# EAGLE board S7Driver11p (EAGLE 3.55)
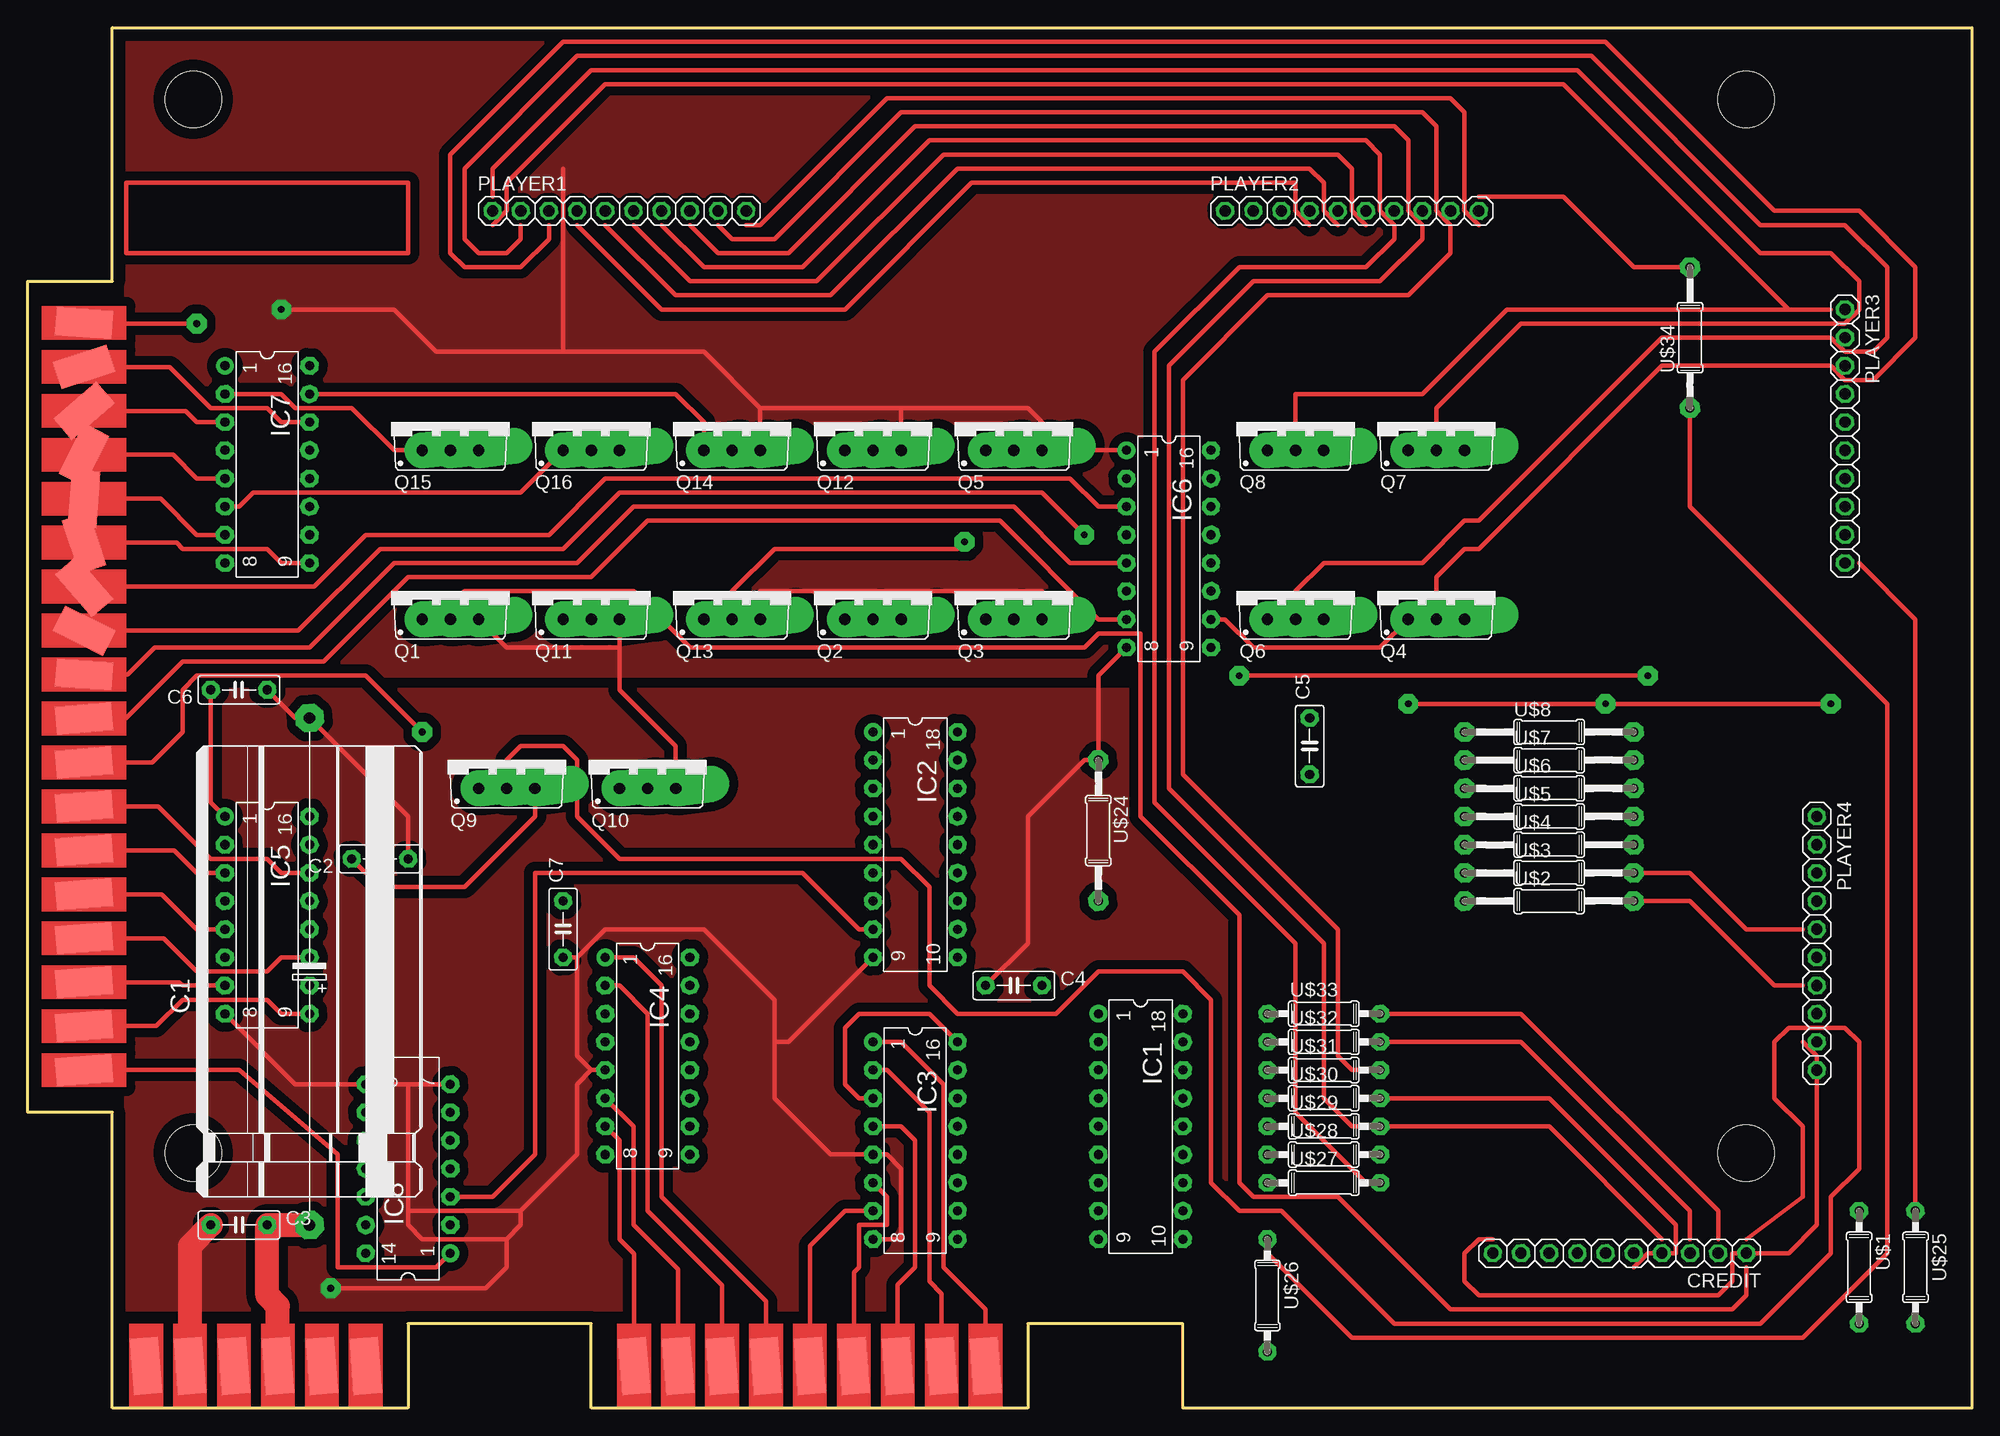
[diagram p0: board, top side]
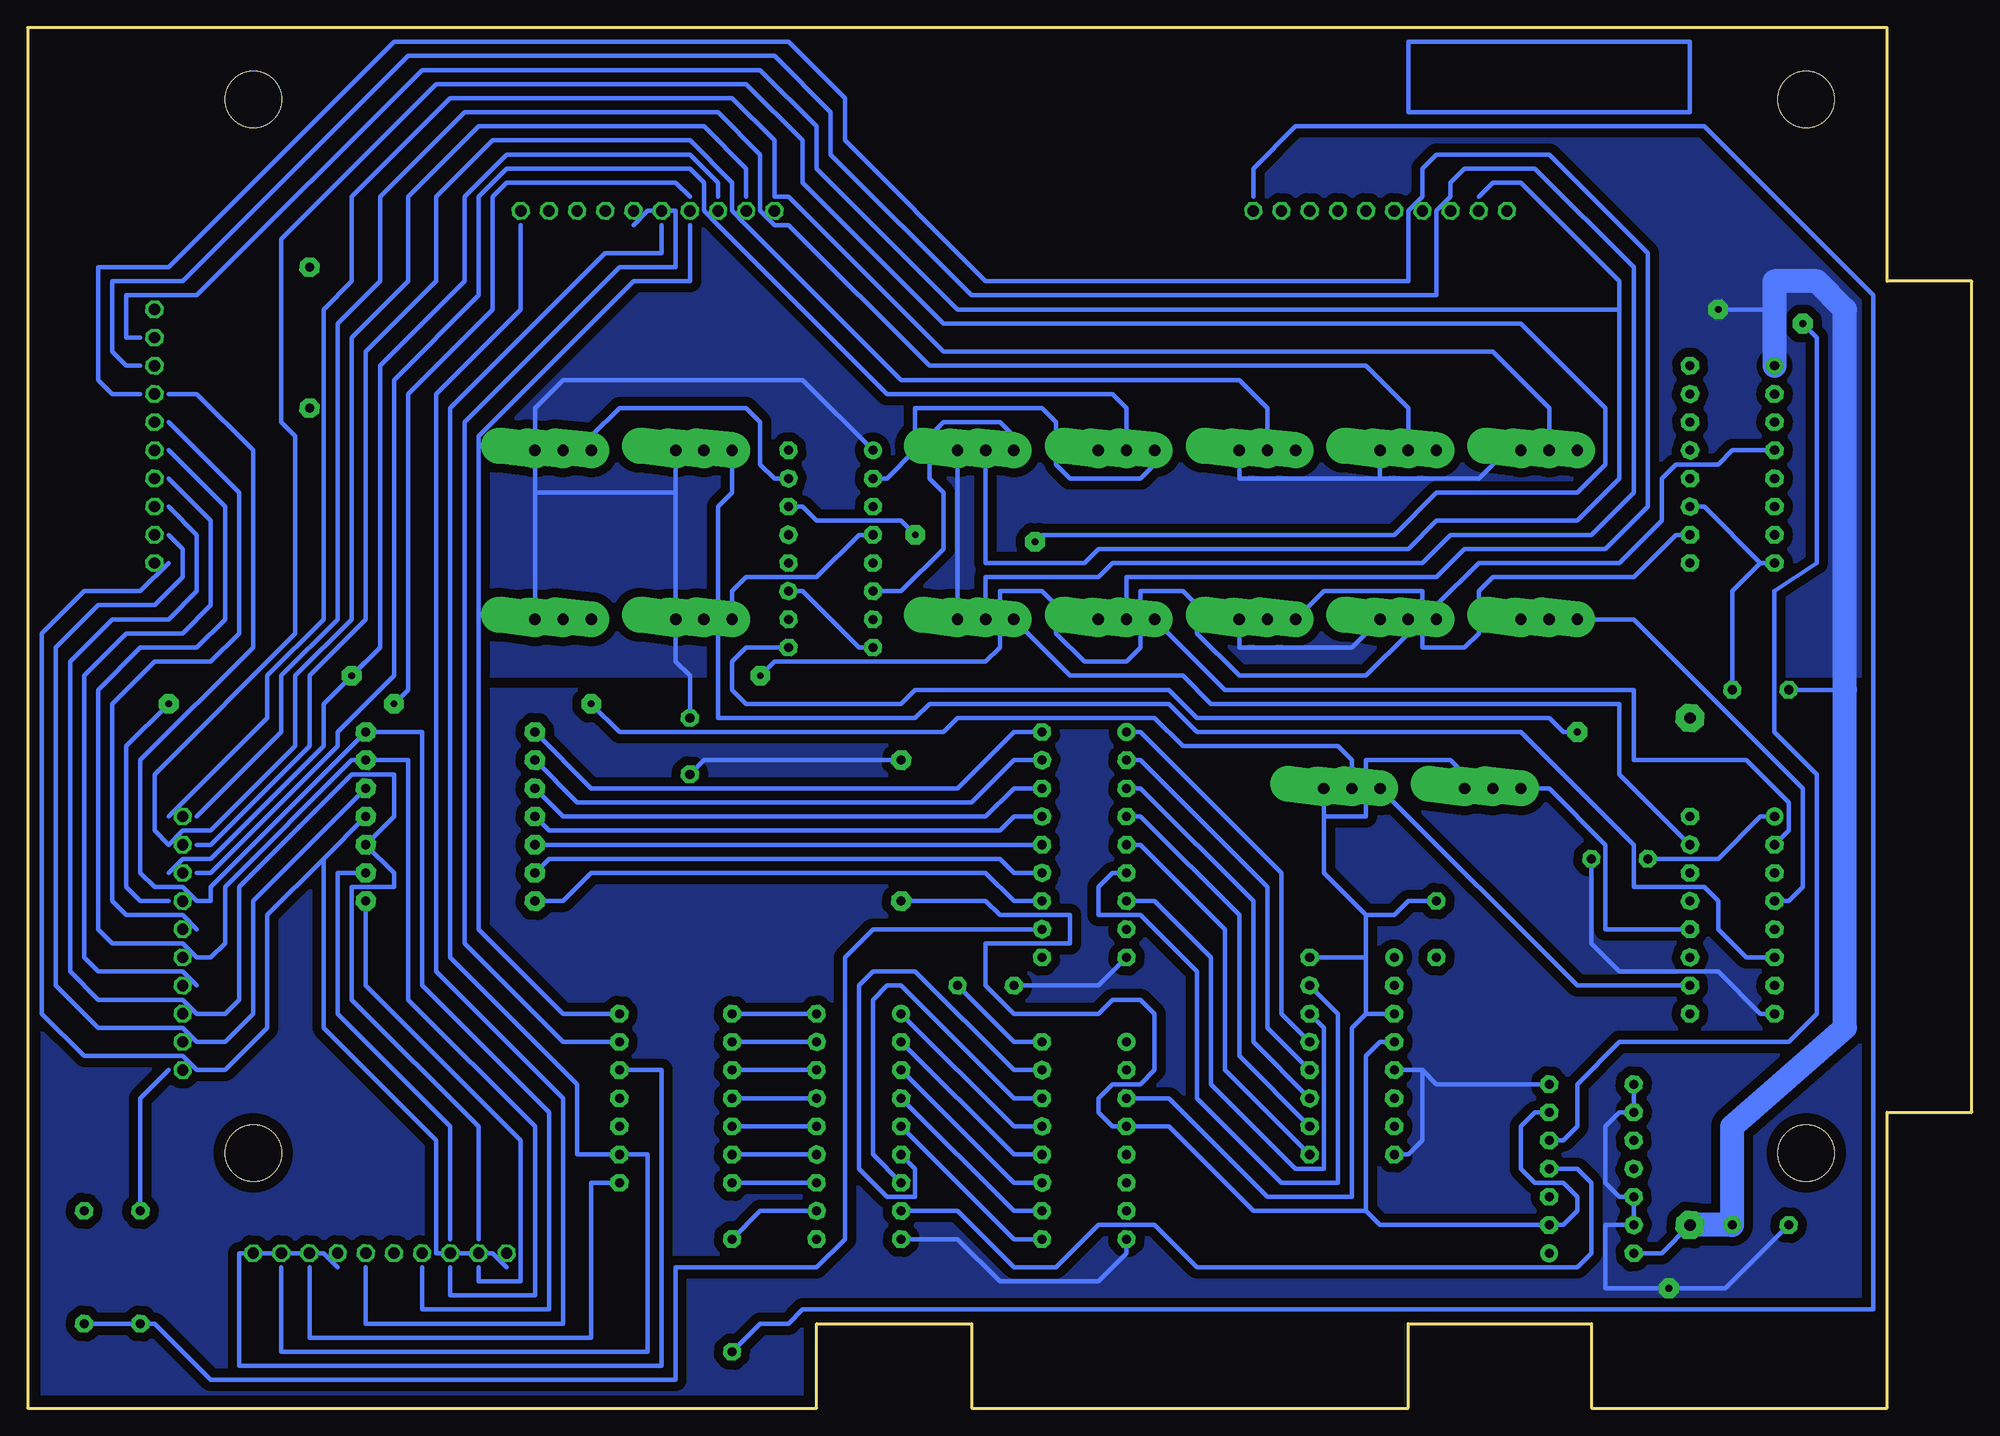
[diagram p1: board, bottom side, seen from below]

Size 175.26 x 124.46 mm. Coordinates in mm from the lower left corner, seen from the top.
Outline: 7.62,0 7.62,26.67 0,26.67 0,101.6 7.62,101.6 7.62,124.46 175.26,124.46 175.26,0 104.14,0 104.14,7.62 90.17,7.62 90.17,0 50.8,0 50.8,7.62 34.29,7.62 34.29,0 7.62,0
Copper layers used: Top, Bottom
Holes 5.08 mm at 14.92,23 154.92,23 154.92,118 14.92,118

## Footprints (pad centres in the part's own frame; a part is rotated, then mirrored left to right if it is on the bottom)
ATINE9 = smd 2.54 x 5.08 rotated 4.3:  0,0 | smd 2.54 x 5.08 rotated 4.4:  3.962,0 | smd 2.54 x 5.08 rotated 4.5:  7.925,0 | smd 2.54 x 5.08 rotated 4.6:  11.887,0 | smd 2.54 x 5.08 rotated 4.7:  15.85,0;  19.812,0 | smd 2.54 x 5.08 rotated 4.8:  23.774,0 | smd 2.54 x 5.08 rotated 4.9:  27.737,0 | smd 2.54 x 5.08 rotated 5:  31.699,0
45 = drill 1.016 pad 2.54 octagon:  0,0;  45.72,0
B2,5 = drill 0.813 pad 1.6 octagon:  -2.54,0;  2.54,0
10 = drill 1.016 pad 1.6 octagon:  -11.43,0;  -8.89,0;  -6.35,0;  -3.81,0;  -1.27,0;  1.27,0;  3.81,0;  6.35,0;  8.89,0;  11.43,0
L18 = drill 0.813 pad 1.6 round:  -10.16,-3.81 | drill 0.813 pad 1.6 octagon:  -7.62,-3.81;  -5.08,-3.81;  -2.54,-3.81;  0,-3.81;  2.54,-3.81;  5.08,-3.81;  7.62,-3.81;  10.16,-3.81;  10.16,3.81;  7.62,3.81;  5.08,3.81;  2.54,3.81;  0,3.81;  -2.54,3.81;  -5.08,3.81;  -7.62,3.81;  -10.16,3.81
L16 = drill 0.813 pad 1.6 round:  -8.89,-3.81 | drill 0.813 pad 1.6 octagon:  -6.35,-3.81;  -3.81,-3.81;  -1.27,-3.81;  1.27,-3.81;  3.81,-3.81;  6.35,-3.81;  8.89,-3.81;  8.89,3.81;  6.35,3.81;  3.81,3.81;  1.27,3.81;  -1.27,3.81;  -3.81,3.81;  -6.35,3.81;  -8.89,3.81
L16' = drill 0.813 pad 1.6 round:  -8.89,-3.81 | drill 0.813 pad 1.6 octagon:  -6.35,-3.81;  6.35,-3.81;  8.89,-3.81;  -3.81,-3.81;  -1.27,-3.81;  3.81,-3.81;  1.27,-3.81;  8.89,3.81;  6.35,3.81;  3.81,3.81;  1.27,3.81;  -1.27,3.81;  -3.81,3.81;  -6.35,3.81;  -8.89,3.81
L14 = drill 0.813 pad 1.6 round:  -7.62,-3.81 | drill 0.813 pad 1.6 octagon:  -5.08,-3.81;  7.62,-3.81;  7.62,3.81;  -2.54,-3.81;  0,-3.81;  5.08,-3.81;  2.54,-3.81;  5.08,3.81;  2.54,3.81;  0,3.81;  -2.54,3.81;  -5.08,3.81;  -7.62,3.81
ATINE6 = smd 2.54 x 5.08 rotated 4.3:  0,0 | smd 2.54 x 5.08 rotated 4.4:  3.962,0 | smd 2.54 x 5.08 rotated 4.5:  7.925,0 | smd 2.54 x 5.08 rotated 4.6:  11.887,0 | smd 2.54 x 5.08 rotated 4.7:  15.85,0;  19.812,0
220BS = drill 1.016 pad 3.251 offset:  -2.54,-2.54;  0,-2.54;  2.54,-2.54
TINE18 = smd 2.54 x 5.08 rotated 4.3:  0,0;  35.662,0 | smd 2.54 x 5.08 rotated 4.4:  3.962,0 | smd 2.54 x 5.08 rotated 4.5:  7.925,0 | smd 2.54 x 5.08 rotated 4.6:  11.887,0 | smd 2.54 x 5.08 rotated 4.7:  15.85,0;  19.812,0 | smd 2.54 x 5.08 rotated 4.8:  23.774,0 | smd 2.54 x 5.08 rotated 4.9:  27.737,0 | smd 2.54 x 5.08 rotated 5:  31.699,0 | smd 2.54 x 5.08 rotated 26.8:  39.624,0 | smd 2.54 x 5.08 rotated 49.3:  43.586,0 | smd 2.54 x 5.08 rotated 71.8:  47.549,0 | smd 2.54 x 5.08 rotated 94.3:  51.511,0 | smd 2.54 x 5.08 rotated 116.8:  55.474,0 | smd 2.54 x 5.08 rotated 139.3:  59.436,0 | smd 2.54 x 5.08 rotated 161.8:  63.398,0 | smd 2.54 x 5.08 rotated 184.3:  67.361,0
07/10 = drill 0.813 pad 1.6 octagon:  -5.08,0;  5.08,0
07/15A = drill 0.813 pad 1.778 octagon:  -7.62,0;  7.62,0
07/12A = drill 0.813 pad 1.778 octagon:  -6.35,0;  6.35,0

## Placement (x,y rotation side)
BCD-IN  PADROW9  [ATINE9]  86.36,3.81 180 top
C1  ELC-45  [45]  25.4,16.51 90 top
C2  C2,5  [B2,5]  31.75,49.53 180 top
C3  C2,5  [B2,5]  19.05,16.51 0 top
C4  C2,5  [B2,5]  88.9,38.1 0 top
C5  C2,5  [B2,5]  115.57,59.69 90 top
C6  C2,5  [B2,5]  19.05,64.77 180 top
C7  C2,5  [B2,5]  48.26,43.18 90 top
CREDIT  PINHD-2X10  [10]  143.51,13.97 180 top
IC1  ULN2803  [L18]  100.33,25.4 270 top
IC2  ULN2803  [L18]  80.01,50.8 270 top
IC3  4511  [L16]  80.01,24.13 270 top
IC4  4511  [L16]  55.88,31.75 270 top
IC5  4050  [L16']  21.59,44.45 270 top
IC6  4050  [L16']  102.87,77.47 270 top
IC7  4050  [L16']  21.59,85.09 270 top
IC8  4081  [L14]  34.29,21.59 90 top
PLAYER1  PINHD-2X10  [10]  53.34,107.95 0 top
PLAYER2  PINHD-2X10  [10]  119.38,107.95 0 top
PLAYER3  PINHD-2X10  [10]  163.83,87.63 270 top
PLAYER4  PINHD-2X10  [10]  161.29,41.91 270 top
POWER  PADROW6  [ATINE6]  30.48,3.81 180 top
Q1  IRF????  [220BS]  38.1,73.66 0 top
Q2  IRF????  [220BS]  76.2,73.66 0 top
Q3  IRF????  [220BS]  88.9,73.66 0 top
Q4  IRF????  [220BS]  127,73.66 0 top
Q5  IRF????  [220BS]  88.9,88.9 0 top
Q6  IRF????  [220BS]  114.3,73.66 0 top
Q7  IRF????  [220BS]  127,88.9 0 top
Q8  IRF????  [220BS]  114.3,88.9 0 top
Q9  IRF????  [220BS]  43.18,58.42 0 top
Q10  IRF????  [220BS]  55.88,58.42 0 top
Q11  IRF????  [220BS]  50.8,73.66 0 top
Q12  IRF????  [220BS]  76.2,88.9 0 top
Q13  IRF????  [220BS]  63.5,73.66 0 top
Q14  IRF????  [220BS]  63.5,88.9 0 top
Q15  IRF????  [220BS]  38.1,88.9 0 top
Q16  IRF????  [220BS]  50.8,88.9 0 top
STROBE  PADROW18  [TINE18]  5.08,30.48 90 top
U$1  R1206  [07/10]  165.1,12.7 270 top
U$2  R1206  [07/15A]  137.16,45.72 0 top
U$3  R1206  [07/15A]  137.16,48.26 0 top
U$4  R1206  [07/15A]  137.16,50.8 0 top
U$5  R1206  [07/15A]  137.16,53.34 0 top
U$6  R1206  [07/15A]  137.16,55.88 0 top
U$7  R1206  [07/15A]  137.16,58.42 0 top
U$8  R1206  [07/15A]  137.16,60.96 0 top
U$24  6.8K  [07/12A]  96.52,52.07 270 top
U$25  R1206  [07/10]  170.18,12.7 270 top
U$26  R1206  [07/10]  111.76,10.16 270 top
U$27  R1206  [07/10]  116.84,20.32 0 top
U$28  R1206  [07/10]  116.84,22.86 0 top
U$29  R1206  [07/10]  116.84,25.4 0 top
U$30  R1206  [07/10]  116.84,27.94 0 top
U$31  R1206  [07/10]  116.84,30.48 0 top
U$32  R1206  [07/10]  116.84,33.02 0 top
U$33  R1206  [07/10]  116.84,35.56 0 top
U$34  R1206  [07/12A]  149.86,96.52 90 top

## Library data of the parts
BCD-IN POWER STROBE = SPECIAL
C1 = DISCRETE
C2-C7 = CAP
CREDIT PLAYER1-PLAYER4 = PINHEAD
IC1-IC4 = ULN
IC5-IC8 = 40XX
Q1-Q16 = TRANS-PW
U$1-U$8 U$24-U$34 = R

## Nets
BLANKING: BCD-IN. IC3. IC4. IC8. U$24.
GND: C1. C2. C3. C4. C5. C6. C7. IC1. IC2. IC3. IC4. IC5. IC6. IC7. IC8. POWER. U$24.
KOMMA1: PLAYER1. U$26.
KOMMA2: PLAYER2. U$34.
KOMMA3: PLAYER3. U$25.
KOMMA4: PLAYER4. U$1.
KOMMA12: IC8. STROBE.
KOMMA34: IC8. STROBE.
N$1: IC1. U$26. U$34.
N$2: IC1. U$27.
N$3: IC1. U$28.
N$4: IC1. U$29.
N$5: IC1. U$30.
N$6: IC1. U$31.
N$7: IC1. U$32.
N$8: IC1. U$33.
N$9: IC2. U$1. U$25.
N$10: IC2. U$4.
N$11: IC2. U$5.
N$12: IC2. U$6.
N$13: IC2. U$7.
N$14: IC2. U$8.
N$15: IC2. U$2.
N$16: IC2. U$3.
N$17: BCD-IN. IC3.
N$18: BCD-IN. IC3.
N$19: BCD-IN. IC3.
N$20: BCD-IN. IC4.
N$21: BCD-IN. IC4.
N$22: BCD-IN. IC4.
N$23: BCD-IN. IC4.
N$24: IC1. IC8.
N$25: BCD-IN. IC3.
N$26: IC5. Q9.
N$27: IC5. Q10.
N$28: IC7. Q11.
N$29: IC6. Q12.
N$30: IC7. Q13.
N$31: IC7. Q14.
N$32: IC7. Q15.
N$33: IC7. Q16.
N$34: IC5. Q1.
N$35: IC5. Q2.
N$36: IC5. Q3.
N$37: IC6. Q4.
N$38: IC6. Q5.
N$39: IC6. Q6.
N$40: IC6. Q7.
N$41: IC5. Q8.
N$48: IC2. IC8.
P1A: CREDIT. PLAYER1. PLAYER2. U$33.
P1B: CREDIT. PLAYER1. PLAYER2. U$32.
P1C: CREDIT. PLAYER1. PLAYER2. U$31.
P1D: CREDIT. PLAYER1. PLAYER2. U$30.
P1E: CREDIT. PLAYER1. PLAYER2. U$29.
P1F: CREDIT. PLAYER1. PLAYER2. U$28.
P1G: CREDIT. PLAYER1. PLAYER2. U$27.
P2A: CREDIT. PLAYER3. PLAYER4. U$8.
P2B: CREDIT. PLAYER3. PLAYER4. U$7.
P2C: CREDIT. PLAYER3. PLAYER4. U$6.
P2D: CREDIT. PLAYER3. PLAYER4. U$5.
P2E: CREDIT. PLAYER3. PLAYER4. U$4.
P2F: CREDIT. PLAYER3. PLAYER4. U$3.
P2G: CREDIT. PLAYER3. PLAYER4. U$2.
STR1: CREDIT. Q1.
STR2: PLAYER1. PLAYER3. Q2.
STR3: PLAYER1. PLAYER3. Q3.
STR4: PLAYER1. PLAYER3. Q4.
STR5: PLAYER1. PLAYER3. Q5.
STR6: PLAYER1. PLAYER3. Q6.
STR7: PLAYER1. PLAYER3. Q7.
STR8: PLAYER1. PLAYER3. Q8.
STR9: CREDIT. Q9.
STR10: PLAYER2. PLAYER4. Q10.
STR11: PLAYER2. PLAYER4. Q11.
STR12: PLAYER2. PLAYER4. Q12.
STR13: PLAYER2. PLAYER4. Q13.
STR14: PLAYER2. PLAYER4. Q14.
STR15: PLAYER2. PLAYER4. Q15.
STR16: PLAYER2. PLAYER4. Q16.
VCC: C1. C2. C3. C4. C5. C6. C7. IC3. IC4. IC5. IC6. IC7. IC8. POWER. Q1. Q2. Q3. Q4. Q5. Q6. Q7. Q8. Q9. Q10. Q11. Q12. Q13. Q14. Q15. Q16.
W1A: IC1. IC3.
W1B: IC1. IC3.
W1C: IC1. IC3.
W1D: IC1. IC3.
W1E: IC1. IC3.
W1F: IC1. IC3.
W1G: IC1. IC3.
W2A: IC2. IC4.
W2B: IC2. IC4.
W2C: IC2. IC4.
W2D: IC2. IC4.
W2E: IC2. IC4.
W2F: IC2. IC4.
W2G: IC2. IC4.
WSTR1: IC5. STROBE.
WSTR2: IC5. STROBE.
WSTR3: IC5. STROBE.
WSTR4: IC6. STROBE.
WSTR5: IC6. STROBE.
WSTR6: IC6. STROBE.
WSTR7: IC6. STROBE.
WSTR8: IC5. STROBE.
WSTR9: IC5. STROBE.
WSTR10: IC5. STROBE.
WSTR11: IC7. STROBE.
WSTR12: IC6. STROBE.
WSTR13: IC7. STROBE.
WSTR14: IC7. STROBE.
WSTR15: IC7. STROBE.
WSTR16: IC7. STROBE.

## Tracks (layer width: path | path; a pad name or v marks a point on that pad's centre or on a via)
BLANKING
  Top 0.406: 76.2,25.4 78.74,25.4 80.01,24.13 80.01,12.7 78.44,11.12 78.44,3.81
  Bottom 0.406: 52.07,33.02 53.34,33.02 54.61,31.75 54.61,17.78 | 54.61,17.78 64.77,17.78 72.39,25.4 76.2,25.4 77.47,25.4 78.74,26.67 78.74,27.94 77.47,29.21 74.93,29.21 73.66,30.48 73.66,35.56 74.93,36.83 77.47,36.83 78.74,35.56 86.36,35.56 88.9,38.1 88.9,41.91 81.28,41.91 81.28,44.45 87.63,44.45 88.9,45.72 U$24. | 54.61,17.78 53.34,16.51 38.1,16.51 36.83,16.51 35.56,17.78 35.56,19.05 36.83,20.32 39.37,20.32 40.64,21.59 40.64,25.4 39.37,26.67 38.1,26.67
GND  (via drill 0.61 pad 1.78)
  Top 0.406: 67.31,33.02 67.31,27.94 72.39,22.86 76.2,22.86 77.47,22.86 78.74,21.59 78.74,15.24 76.2,15.24 | 67.31,33.02 67.31,36.83 60.96,43.18 52.07,43.18 49.53,40.64 | 49.53,40.64 49.53,31.75 50.8,30.48 | 50.8,30.48 52.07,30.48 | 17.78,35.56 24.13,29.21 30.48,29.21 34.29,29.21 | 34.29,29.21 38.1,29.21 | 67.31,33.02 68.58,33.02 76.2,40.64 | 99.06,68.58 96.52,66.04 96.52,58.42 95.25,58.42 90.17,53.34 90.17,41.91 86.36,38.1 | 49.53,40.64 48.26,40.64 | 50.8,30.48 49.53,29.21 49.53,22.86 44.45,17.78 | 44.45,17.78 44.45,16.51 43.18,15.24 | 43.18,15.24 35.56,15.24 34.29,16.51 34.29,17.78 | 34.29,17.78 34.29,29.21 | 44.45,17.78 34.29,17.78 | 21.59,64.77 24.13,62.23 C1. 34.29,53.34 34.29,49.53 | v27.3,10.79 41.27,10.79 43.18,12.7 43.18,15.24
  Top 2.184: 14.63,3.81 14.63,14.63 16.51,16.51
  Bottom 0.406: 25.4,81.28 24.13,81.28 19.05,76.2 | 19.05,76.2 17.78,76.2 | 30.48,29.21 30.48,26.67 31.75,26.67 33.02,25.4 33.02,20.32 31.75,19.05 30.48,19.05 30.48,16.51 33.02,16.51 33.02,10.79 v27.3,10.79 22.23,10.79 16.51,16.51 | 38.1,29.21 48.26,29.21 49.53,30.48 | 52.07,30.48 49.53,30.48 | 52.07,22.86 50.8,22.86 49.53,24.13 49.53,30.48 | 106.68,73.66 105.41,73.66 100.33,68.58 99.06,68.58 | 76.2,15.24 76.2,13.97 78.74,11.43 87.63,11.43 91.44,15.24 96.52,15.24 | 19.05,76.2 21.59,73.66 21.59,64.77 | 17.78,35.56 19.05,35.56 22.86,39.37 31.75,39.37 34.29,41.91 34.29,49.53 | 96.52,58.42 114.3,58.42 115.57,57.15 | 76.2,40.64 78.74,38.1 86.36,38.1
  pour Bottom (isolate 0.8): 8.89,8.89 8.89,64.77 137.16,64.77 137.16,91.44 50.8,91.44 50.8,124.46 175.26,124.46 175.26,0 104.14,0 104.14,8.89
  pour Top (isolate 0.8): 8.89,8.89 8.89,64.77 140.97,64.77 140.97,124.46 175.26,124.46 175.26,0 104.14,0 104.14,8.89
KOMMA1
  Bottom 0.406: U$26. 109.22,7.62 106.68,7.62 105.41,8.89 8.89,8.89 8.89,100.33 24.13,115.57 60.96,115.57 64.77,111.76 64.77,109.22
KOMMA2
  Top 0.406: 130.81,109.22 138.43,109.22 144.78,102.87 U$34.
KOMMA3
  Top 0.406: 165.1,76.2 170.18,71.12 170.18,17.78
KOMMA4
  Bottom 0.406: 165.1,17.78 165.1,27.94 162.56,30.48
KOMMA12  (via drill 0.61 pad 1.78)
  Top 0.406: STROBE. 5.08,97.79 v15.24,97.79
  Bottom 0.406: 38.1,24.13 36.83,24.13 35.56,25.4 35.56,29.21 31.75,33.02 16.51,33.02 13.97,35.56 13.97,57.15 17.78,60.96 17.78,73.66 13.97,76.2 13.97,96.52 v15.24,97.79
KOMMA34
  Top 0.406: 5.08,30.48 19.05,30.48 27.94,22.86 27.94,12.7 36.83,12.7 38.1,13.97
N$1
  Top 0.406: 111.76,15.24 111.76,13.97 119.38,6.35 160.02,6.35 167.64,13.97 167.64,63.5 149.86,81.28 149.86,90.17
  Bottom 0.406: 104.14,17.78 109.22,17.78 111.76,15.24
N$2
  Bottom 0.406: 104.14,20.32 111.76,20.32
N$3
  Bottom 0.406: 104.14,22.86 111.76,22.86
N$4
  Bottom 0.406: 104.14,25.4 111.76,25.4
N$5
  Bottom 0.406: 104.14,27.94 111.76,27.94
N$6
  Bottom 0.406: 104.14,30.48 111.76,30.48
N$7
  Bottom 0.406: 104.14,33.02 111.76,33.02
N$8
  Bottom 0.406: IC1. 111.76,35.56
N$9
  Bottom 0.406: U$25. U$1. 163.83,7.62 158.75,2.54 116.84,2.54 116.84,12.7 104.14,12.7 101.6,15.24 101.6,40.64 99.06,43.18 83.82,43.18
N$10
  Bottom 0.406: 83.82,50.8 129.54,50.8
N$11
  Bottom 0.406: 83.82,53.34 86.36,53.34 87.63,52.07 128.27,52.07 129.54,53.34
N$12
  Bottom 0.406: 83.82,55.88 86.36,55.88 88.9,53.34 127,53.34 129.54,55.88
N$13
  Bottom 0.406: 83.82,58.42 86.36,58.42 90.17,54.61 125.73,54.61 129.54,58.42
N$14
  Bottom 0.406: IC2. 86.36,60.96 91.44,55.88 124.46,55.88 129.54,60.96
N$15
  Bottom 0.406: 83.82,45.72 86.36,45.72 88.9,48.26 124.46,48.26 127,45.72 129.54,45.72
N$16
  Bottom 0.406: 83.82,48.26 86.36,48.26 87.63,49.53 128.27,49.53 129.54,48.26
N$17
  Top 0.406: 82.4,3.81 82.4,10.31 81.28,11.43 81.28,26.67 77.47,30.48 76.2,30.48
N$18
  Top 0.406: 76.2,20.32 77.47,19.05 77.47,16.51 74.93,16.51 74.93,12.7 74.47,12.24 74.47,3.81
N$19
  Top 0.406: 70.51,3.81 70.51,14.63 73.66,17.78 76.2,17.78
N$20
  Top 0.406: 66.55,3.81 66.55,9.65 57.15,19.05 57.15,38.1 54.61,40.64 52.07,40.64
N$21
  Top 0.406: 62.59,3.81 62.59,11.07 55.88,17.78 55.88,35.56 53.34,38.1 52.07,38.1
N$22
  Top 0.406: 58.62,3.81 58.62,12.5 54.61,16.51 54.61,25.4 52.07,27.94
N$23
  Top 0.406: BCD-IN. 54.66,13.92 53.34,15.24 53.34,24.13 52.07,25.4
N$24
  Bottom 0.406: 38.1,21.59 35.56,21.59 34.29,20.32 34.29,13.97 35.56,12.7 69.85,12.7 73.66,16.51 78.74,16.51 82.55,12.7 86.36,12.7 91.44,17.78 96.52,17.78
N$25
  Top 0.406: 86.36,3.81 86.36,8.89 82.55,12.7 82.55,29.21 78.74,33.02 76.2,33.02
N$26
  Bottom 0.406: 25.4,43.18 33.02,43.18 33.02,50.8 38.1,55.88 40.64,55.88
N$27
  Bottom 0.406: 25.4,38.1 35.56,38.1 53.34,55.88
N$28
  Bottom 0.406: 17.78,86.36 21.59,86.36 22.86,85.09 26.67,85.09 27.94,83.82 27.94,80.01 31.75,76.2 44.45,76.2 48.26,72.39 48.26,71.12
N$29
  Bottom 0.406: 73.66,86.36 73.66,85.09 74.93,83.82 81.28,83.82 82.55,85.09 82.55,88.9 83.82,90.17 95.25,90.17 95.25,86.36 97.79,83.82 99.06,83.82
N$30
  Bottom 0.406: 25.4,78.74 26.67,78.74 30.48,74.93 43.18,74.93 44.45,73.66 44.45,69.85 45.72,68.58 49.53,68.58 49.53,73.66 58.42,73.66 60.96,71.12
N$31
  Top 0.406: 25.4,91.44 58.42,91.44 60.96,88.9 60.96,86.36
N$32
  Top 0.406: 17.78,91.44 22.86,91.44 24.13,90.17 29.21,90.17 33.02,86.36 35.56,86.36
N$33
  Top 0.406: 17.78,81.28 19.05,81.28 20.32,82.55 44.45,82.55 48.26,86.36
N$34
  Bottom 0.406: 17.78,45.72 16.51,45.72 15.24,46.99 15.24,55.88 30.48,71.12 35.56,71.12
N$35
  Bottom 0.406: 17.78,50.8 16.51,52.07 16.51,54.61 20.32,58.42 30.48,58.42 30.48,64.77 67.31,64.77 73.66,71.12
N$36
  Bottom 0.406: 25.4,50.8 31.75,57.15 31.75,63.5 68.58,63.5 71.12,66.04 81.28,66.04 86.36,71.12
N$37
  Top 0.406: 106.68,71.12 107.95,71.12 110.49,68.58 121.92,68.58 124.46,71.12
N$38
  Bottom 0.406: 86.36,86.36 86.36,87.63 87.63,88.9 92.71,88.9 93.98,87.63 93.98,83.82 92.71,82.55 92.71,77.47 96.52,73.66 99.06,73.66
N$39
  Bottom 0.406: 99.06,78.74 100.33,78.74 104.14,74.93 110.49,74.93 111.76,73.66 111.76,71.12
N$40
  Bottom 0.406: 106.68,83.82 107.95,83.82 109.22,85.09 109.22,88.9 110.49,90.17 121.92,90.17 124.46,87.63 124.46,86.36
N$41
  Bottom 0.406: 17.78,40.64 20.32,40.64 22.86,43.18 22.86,45.72 24.13,46.99 30.48,46.99 30.48,50.8 40.64,60.96 69.85,60.96 72.39,63.5 93.98,63.5 95.25,62.23 113.03,62.23 113.03,81.28 111.76,82.55 111.76,86.36
N$42
  Bottom 0.406: 25.4,116.84 25.4,123.19 50.8,123.19 50.8,116.84 25.4,116.84
N$43
  Top 0.406: 8.89,104.14 8.89,110.49 34.29,110.49 34.29,104.14 8.89,104.14
N$48
  Top 0.406: 38.1,19.05 41.91,19.05 45.72,22.86 45.72,48.26 69.85,48.26 74.93,43.18 76.2,43.18
P1A
  Top 0.406: 152.4,15.24 152.4,17.78 134.62,35.56 U$33. | 115.57,106.68 114.3,107.95 114.3,110.49 85.09,110.49 73.66,99.06 57.15,99.06 49.53,106.68
  Bottom 0.406: 115.57,106.68 115.57,101.6 120.65,101.6 134.62,87.63 134.62,43.18 127,35.56 U$33.
P1B
  Top 0.406: 149.86,15.24 149.86,17.78 134.62,33.02 U$32. | 54.61,106.68 59.69,101.6 71.12,101.6 82.55,113.03 118.11,113.03 119.38,111.76 119.38,107.95 120.65,106.68
  Bottom 0.406: 120.65,106.68 119.38,107.95 116.84,107.95 116.84,102.87 121.92,102.87 135.89,88.9 135.89,41.91 127,33.02 U$32.
P1C
  Top 0.406: 62.23,106.68 63.5,105.41 67.31,105.41 78.74,116.84 125.73,116.84 127,115.57 127,107.95 128.27,106.68 128.27,104.14 124.46,100.33 111.76,100.33 104.14,92.71 104.14,57.15 118.11,43.18 118.11,31.75 119.38,30.48 U$31.
  Bottom 0.406: 147.32,12.7 148.59,13.97 156.21,13.97 156.21,3.81 118.11,3.81 118.11,30.48 U$31.
P1D
  Top 0.406: 130.81,106.68 129.54,107.95 129.54,116.84 128.27,118.11 77.47,118.11 66.04,106.68 64.77,106.68 | U$30. 137.16,27.94 148.59,16.51 148.59,13.97 146.05,13.97 144.78,12.7
  Bottom 0.406: 144.78,12.7 144.78,7.62 127,7.62 127,27.94 138.43,39.37 138.43,91.44 130.81,99.06 130.81,106.68
P1E
  Top 0.406: 147.32,15.24 137.16,25.4 U$29. 119.38,25.4 116.84,27.94 116.84,41.91 102.87,55.88 102.87,93.98 110.49,101.6 121.92,101.6 125.73,105.41 125.73,106.68 124.46,107.95 124.46,114.3 123.19,115.57 80.01,115.57 68.58,104.14 62.23,104.14 59.69,106.68
P1F
  Top 0.406: 118.11,106.68 116.84,107.95 116.84,110.49 115.57,111.76 83.82,111.76 72.39,100.33 58.42,100.33 52.07,106.68
  Bottom 0.406: 152.4,12.7 152.4,5.08 119.38,5.08 119.38,22.86 U$28. 125.73,22.86 125.73,29.21 137.16,40.64 137.16,90.17 123.19,104.14 118.11,104.14 118.11,106.68
P1G
  Top 0.406: 57.15,106.68 60.96,102.87 69.85,102.87 81.28,114.3 120.65,114.3 121.92,113.03 121.92,107.95 123.19,106.68 123.19,105.41 120.65,102.87 109.22,102.87 101.6,95.25 101.6,54.61 114.3,41.91 114.3,26.67 120.65,20.32 U$27.
  Bottom 0.406: U$27. 124.46,20.32 124.46,6.35 149.86,6.35 149.86,12.7
P2A
  Bottom 0.406: 139.7,12.7 139.7,8.89 128.27,8.89 128.27,26.67 139.7,38.1 139.7,60.96 U$8. 158.75,46.99 158.75,45.72 160.02,45.72 161.29,46.99 163.83,46.99 165.1,48.26 165.1,58.42 154.94,68.58 154.94,86.36 160.02,91.44 162.56,91.44
P2B
  Bottom 0.406: 137.16,12.7 137.16,10.16 129.54,10.16 129.54,25.4 140.97,36.83 140.97,58.42 U$7. 146.05,58.42 157.48,46.99 157.48,41.91 158.75,40.64 160.02,40.64 161.29,41.91 167.64,41.91 168.91,43.18 168.91,64.77 165.1,68.58 160.02,68.58 157.48,71.12 157.48,81.28 162.56,86.36
P2C
  Top 0.406: 160.02,33.02 161.29,31.75 161.29,16.51 158.75,13.97 153.67,13.97 153.67,11.43 152.4,10.16 130.81,10.16 129.54,11.43 129.54,13.97 130.81,15.24 132.08,15.24
  Bottom 0.406: U$6. 154.94,45.72 154.94,35.56 157.48,33.02 160.02,33.02 161.29,34.29 168.91,34.29 172.72,38.1 172.72,68.58 168.91,72.39 163.83,72.39 161.29,74.93 161.29,77.47 162.56,78.74
P2D
  Bottom 0.406: 132.08,12.7 133.35,13.97 138.43,13.97 138.43,24.13 148.59,34.29 148.59,49.53 | 148.59,49.53 U$5. | 162.56,76.2 165.1,73.66 170.18,73.66 173.99,69.85 173.99,35.56 170.18,31.75 161.29,31.75 160.02,30.48 157.48,30.48 153.67,34.29 153.67,44.45 148.59,49.53
P2E
  Bottom 0.406: 134.62,15.24 134.62,25.4 146.05,36.83 146.05,46.99 142.24,46.99 142.24,48.26 U$4. 142.24,53.34 142.24,57.15 146.05,57.15 156.21,46.99 156.21,36.83 157.48,35.56 160.02,35.56 161.29,36.83 168.91,36.83 171.45,39.37 171.45,67.31 167.64,71.12 162.56,71.12 160.02,73.66 160.02,78.74 162.56,81.28
P2F
  Top 0.406: 160.02,43.18 154.94,43.18 149.86,48.26 U$3.
  Bottom 0.406: 137.16,15.24 137.16,25.4 147.32,35.56 147.32,48.26 U$3. | 162.56,88.9 156.21,82.55 156.21,69.85 158.75,67.31 163.83,67.31 167.64,63.5 167.64,45.72 166.37,44.45 161.29,44.45 160.02,43.18
P2G
  Top 0.406: U$2. 149.86,45.72 157.48,38.1 160.02,38.1
  Bottom 0.406: 134.62,12.7 134.62,11.43 130.81,11.43 130.81,24.13 144.78,38.1 U$2. | 162.56,83.82 158.75,80.01 158.75,72.39 161.29,69.85 166.37,69.85 170.18,66.04 170.18,40.64 168.91,39.37 161.29,39.37 160.02,38.1
STR1
  Top 0.406: 154.94,12.7 154.94,10.16 153.67,8.89 128.27,8.89 118.11,19.05 110.49,19.05 109.22,20.32 109.22,44.45 100.33,53.34 100.33,69.85 96.52,69.85 95.25,68.58 59.69,68.58 54.61,73.66 39.37,73.66 38.1,72.39 38.1,71.12
STR2
  Bottom 0.406: 165.1,91.44 167.64,91.44 168.91,92.71 168.91,102.87 162.56,102.87 142.24,123.19 106.68,123.19 101.6,118.11 101.6,114.3 88.9,101.6 50.8,101.6 50.8,107.95 49.53,109.22 49.53,111.76 48.26,113.03 38.1,113.03 29.21,104.14 29.21,81.28 33.02,77.47 45.72,77.47 48.26,74.93 76.2,74.93 76.2,71.12
STR3
  Bottom 0.406: 165.1,93.98 166.37,93.98 167.64,95.25 167.64,101.6 161.29,101.6 140.97,121.92 107.95,121.92 102.87,116.84 102.87,113.03 90.17,100.33 48.26,100.33 48.26,107.95 46.99,109.22 46.99,110.49 45.72,111.76 39.37,111.76 30.48,102.87 30.48,82.55 34.29,78.74 46.99,78.74 49.53,76.2 77.47,76.2 78.74,74.93 88.9,74.93 88.9,71.12
STR4
  Top 0.406: 127,71.12 127,74.93 129.54,77.47 130.81,77.47 147.32,93.98 162.56,93.98 163.83,92.71 166.37,92.71 170.18,96.52 170.18,102.87 165.1,107.95 157.48,107.95 142.24,123.19 48.26,123.19 38.1,113.03 38.1,104.14 39.37,102.87 44.45,102.87 46.99,105.41 46.99,106.68
STR5
  Bottom 0.406: 165.1,96.52 166.37,96.52 166.37,100.33 160.02,100.33 139.7,120.65 109.22,120.65 104.14,115.57 104.14,111.76 91.44,99.06 46.99,99.06 31.75,99.06 | 88.9,86.36 88.9,76.2 80.01,76.2 78.74,77.47 50.8,77.47 48.26,80.01 35.56,80.01 31.75,83.82 31.75,99.06 | 31.75,99.06 31.75,101.6 40.64,110.49 43.18,110.49 44.45,109.22
STR6
  Top 0.406: 114.3,71.12 114.3,73.66 116.84,76.2 125.73,76.2 129.54,80.01 130.81,80.01 147.32,96.52 162.56,96.52 163.83,95.25 166.37,95.25 167.64,96.52 167.64,102.87 163.83,106.68 156.21,106.68 140.97,121.92 49.53,121.92 39.37,111.76 39.37,105.41 40.64,104.14 43.18,104.14 44.45,105.41 44.45,106.68
STR7
  Top 0.406: 127,86.36 127,90.17 134.62,97.79 163.83,97.79 165.1,99.06 165.1,101.6 162.56,104.14 156.21,104.14 139.7,120.65 50.8,120.65 41.91,111.76 41.91,109.22
STR8
  Top 0.406: 158.75,99.06 162.56,99.06 | 158.75,99.06 133.35,99.06 125.73,91.44 114.3,91.44 114.3,86.36 | 41.91,106.68 43.18,107.95 43.18,110.49 52.07,119.38 138.43,119.38 158.75,99.06
STR9
  Top 0.406: 154.94,15.24 160.02,19.05 160.02,25.4 157.48,27.94 157.48,33.02 158.75,34.29 163.83,34.29 165.1,33.02 165.1,21.59 162.56,19.05 162.56,13.97 156.21,7.62 123.19,7.62 113.03,17.78 109.22,17.78 106.68,20.32 106.68,36.83 104.14,39.37 96.52,39.37 92.71,35.56 83.82,35.56 81.28,38.1 81.28,46.99 78.74,49.53 53.34,49.53 49.53,53.34 49.53,58.42 48.26,59.69 44.45,59.69 43.18,58.42 43.18,55.88
STR10  (via drill 0.61 pad 1.78)
  Top 0.406: v162.56,63.5 v142.24,63.5 v124.46,63.5
  Bottom 0.406: 115.57,109.22 116.84,110.49 132.08,110.49 133.35,109.22 133.35,99.06 140.97,91.44 140.97,64.77 v142.24,63.5 | 162.56,45.72 165.1,45.72 166.37,46.99 166.37,59.69 v162.56,63.5 | v124.46,63.5 121.92,60.96 92.71,60.96 91.44,62.23 73.66,62.23 71.12,59.69 57.15,59.69 55.88,58.42 55.88,55.88
STR11  (via drill 0.61 pad 1.78)
  Top 0.406: v109.22,66.04 v146.05,66.04
  Bottom 0.406: 162.56,48.26 161.29,49.53 158.75,49.53 148.59,59.69 148.59,63.5 143.51,68.58 | 143.51,68.58 143.51,93.98 135.89,101.6 135.89,109.22 132.08,113.03 115.57,113.03 113.03,110.49 113.03,109.22 | 50.8,71.12 50.8,69.85 54.61,66.04 66.04,66.04 69.85,69.85 69.85,72.39 71.12,73.66 74.93,73.66 74.93,68.58 76.2,67.31 80.01,67.31 82.55,69.85 82.55,72.39 83.82,73.66 87.63,73.66 87.63,68.58 88.9,67.31 107.95,67.31 v109.22,66.04 | v146.05,66.04 143.51,68.58
STR12
  Bottom 0.406: 160.02,48.26 158.75,48.26 147.32,59.69 147.32,60.96 142.24,66.04 142.24,92.71 134.62,100.33 134.62,109.22 132.08,111.76 115.57,111.76 114.3,110.49 114.3,107.95 113.03,106.68 97.79,91.44 77.47,91.44 76.2,90.17 76.2,86.36
STR13  (via drill 0.61 pad 1.78)
  Top 0.406: v84.45,78.11 83.82,77.47 67.31,77.47 63.5,73.66 63.5,71.12
  Bottom 0.406: 110.49,109.22 110.49,111.76 114.3,115.57 134.62,115.57 140.97,109.22 140.97,101.6 146.05,96.52 146.05,71.12 151.13,66.04 151.13,59.69 158.75,52.07 161.29,52.07 162.56,50.8 163.83,52.07 163.83,57.15 151.13,69.85 151.13,87.63 152.4,88.9 152.4,105.41 138.43,119.38 110.49,119.38 105.41,114.3 105.41,110.49 92.71,97.79 40.64,97.79 33.02,90.17 33.02,85.09 35.56,82.55 48.26,82.55 52.07,78.74 83.82,78.74 v84.45,78.11
STR14
  Bottom 0.406: 160.02,50.8 158.75,50.8 149.86,59.69 149.86,66.04 144.78,71.12 144.78,95.25 138.43,101.6 138.43,109.22 133.35,114.3 115.57,114.3 111.76,110.49 111.76,107.95 110.49,106.68 96.52,92.71 66.04,92.71 63.5,90.17 63.5,86.36
STR15
  Bottom 0.406: 162.56,53.34 153.67,62.23 153.67,66.04 148.59,71.12 148.59,99.06 146.05,101.6 146.05,109.22 137.16,118.11 111.76,118.11 107.95,114.3 107.95,109.22 106.68,109.22 92.71,95.25 43.18,95.25 38.1,90.17 38.1,86.36
STR16
  Bottom 0.406: 160.02,53.34 152.4,60.96 152.4,66.04 147.32,71.12 147.32,97.79 143.51,101.6 143.51,109.22 135.89,116.84 113.03,116.84 109.22,113.03 109.22,107.95 107.95,106.68 106.68,106.68 93.98,93.98 54.61,93.98 50.8,90.17 50.8,86.36
VCC  (via drill 0.61 pad 1.78)
  Top 0.406: 66.04,90.17 Q14. | 66.04,90.17 78.74,90.17 | 78.74,90.17 Q12. | 78.74,90.17 90.17,90.17 91.44,88.9 Q5. 99.06,86.36 | Q3. 91.44,73.66 78.74,73.66 | 78.74,73.66 Q2. | Q13. 66.04,73.66 78.74,73.66 | 53.34,68.58 Q11. | 53.34,68.58 43.18,68.58 Q1. | Q10. 58.42,59.69 53.34,64.77 53.34,68.58 | C2. 31.75,46.99 39.37,46.99 45.72,53.34 Q9. | C6. 16.51,54.61 17.78,53.34 | 76.2,27.94 74.93,27.94 73.66,29.21 73.66,34.29 74.93,35.56 81.28,35.56 IC3. | 66.04,90.17 60.96,95.25 48.26,95.25 | 48.26,95.25 36.83,95.25 33.02,99.06 v22.86,99.06 | 48.26,95.25 48.26,111.76
  Top 2.184: 22.55,3.81 22.55,9.2 21.59,10.16 C3. 25.4,16.51
  Bottom 0.406: 54.61,35.56 52.07,35.56 | 54.61,35.56 55.88,34.29 55.88,19.05 63.5,19.05 72.39,27.94 76.2,27.94 | 58.42,53.34 58.42,48.26 54.61,44.45 | 58.42,53.34 Q10. | 54.61,44.45 54.61,40.64 | 54.61,40.64 54.61,35.56 | Q15. 41.91,86.36 44.45,83.82 53.34,83.82 | 53.34,83.82 Q16. | Q14. 66.04,83.82 53.34,83.82 | Q5. Q3. | Q13. 66.04,68.58 55.88,68.58 Q11. | 99.06,86.36 105.41,92.71 127,92.71 129.54,90.17 Q7. 129.54,82.55 | 129.54,82.55 116.84,82.55 | 116.84,82.55 Q8. | 116.84,82.55 Q6. 116.84,67.31 115.57,66.04 C5. | 129.54,82.55 Q4. | 11.43,64.77 C6. | C2. 22.86,49.53 19.05,53.34 17.78,53.34 | Q9. 45.72,57.15 46.99,58.42 54.61,58.42 54.61,53.34 58.42,53.34 | 54.61,40.64 IC4. | IC3. 86.36,33.02 C4. | 54.61,44.45 52.07,44.45 50.8,45.72 C7. | 25.4,16.51 27.94,13.97 IC8. | 17.78,99.06 v22.86,99.06
  Bottom 2.184: 17.78,93.98 17.78,99.06 17.78,101.6 13.97,101.6 11.43,99.06 11.43,64.77 11.43,34.29 21.59,25.4 C3. 25.4,16.51
  pour Top (isolate 0.8): 8.89,123.19 8.89,66.04 144.78,66.04 144.78,35.56 171.45,35.56 171.45,123.19 138.43,123.19
  pour Bottom (isolate 0.8): 8.89,124.46 8.89,66.04 143.51,66.04 143.51,124.46
W1A
  Bottom 0.406: 83.82,25.4 86.36,25.4 96.52,35.56
W1B
  Bottom 0.406: 83.82,22.86 86.36,22.86 96.52,33.02
W1C
  Bottom 0.406: 83.82,20.32 86.36,20.32 96.52,30.48
W1D
  Bottom 0.406: 83.82,17.78 86.36,17.78 96.52,27.94
W1E
  Bottom 0.406: 83.82,15.24 86.36,15.24 96.52,25.4
W1F
  Bottom 0.406: 83.82,30.48 86.36,30.48 95.25,39.37 99.06,39.37 100.33,38.1 100.33,21.59 97.79,19.05 95.25,19.05 95.25,21.59 96.52,22.86
W1G
  Bottom 0.406: 83.82,27.94 86.36,27.94 96.52,38.1 97.79,38.1 99.06,36.83 99.06,22.86 96.52,20.32
W2A
  Bottom 0.406: 59.69,33.02 62.23,35.56 62.23,48.26 74.93,60.96 76.2,60.96
W2B
  Bottom 0.406: 59.69,30.48 63.5,34.29 63.5,46.99 74.93,58.42 76.2,58.42
W2C
  Bottom 0.406: 59.69,27.94 64.77,33.02 64.77,45.72 74.93,55.88 76.2,55.88
W2D
  Bottom 0.406: 59.69,25.4 66.04,31.75 66.04,44.45 74.93,53.34 76.2,53.34
W2E
  Bottom 0.406: 59.69,22.86 67.31,30.48 67.31,43.18 74.93,50.8 76.2,50.8
W2F
  Bottom 0.406: 59.69,38.1 57.15,35.56 57.15,20.32 62.23,20.32 69.85,27.94 69.85,39.37 74.93,44.45 78.74,44.45 78.74,46.99 77.47,48.26 76.2,48.26
W2G
  Bottom 0.406: 59.69,35.56 58.42,34.29 58.42,21.59 60.96,21.59 68.58,29.21 68.58,40.64 73.66,45.72 76.2,45.72
WSTR1
  Top 0.406: 5.08,46.33 12.09,46.33 15.24,43.18 17.78,43.18
WSTR2
  Top 0.406: 5.08,50.29 13.21,50.29 15.24,48.26 17.78,48.26
WSTR3
  Top 0.406: 5.08,54.25 11.79,54.25 16.51,49.53 21.59,49.53 22.86,48.26 25.4,48.26
WSTR4  (via drill 0.61 pad 1.78)
  Top 0.406: 5.08,58.22 11.23,58.22 13.97,60.96 13.97,64.77 15.24,66.04 30.48,66.04 v35.56,60.96
  Bottom 0.406: 106.68,68.58 110.49,68.58 111.76,67.31 111.76,64.77 110.49,63.5 96.52,63.5 95.25,64.77 72.39,64.77 69.85,62.23 38.1,62.23 36.83,60.96 v35.56,60.96
WSTR5
  Top 0.406: 99.06,71.12 96.52,71.12 87.63,80.01 55.88,80.01 50.8,74.93 34.29,74.93 26.67,67.31 13.97,67.31 8.84,62.18 5.08,62.18
WSTR6
  Top 0.406: 99.06,76.2 93.98,76.2 88.9,81.28 54.61,81.28 49.53,76.2 33.02,76.2 25.4,68.58 11.43,68.58 8.99,66.14 5.08,66.14
WSTR7  (via drill 0.61 pad 1.78)
  Top 0.406: 5.08,70.1 24.38,70.1 31.75,77.47 48.26,77.47 53.34,82.55 91.44,82.55 v95.25,78.74
  Bottom 0.406: v95.25,78.74 96.52,80.01 104.14,80.01 105.41,81.28 106.68,81.28
WSTR8
  Top 0.406: 5.08,38.41 13.66,38.41 13.97,38.1 17.78,38.1
WSTR9
  Top 0.406: 5.08,42.37 12.24,42.37 15.24,39.37 21.59,39.37 22.86,40.64 25.4,40.64
WSTR10
  Top 0.406: 5.08,34.44 11.58,34.44 13.97,36.83 21.59,36.83 22.86,35.56 25.4,35.56
WSTR11
  Top 0.406: 5.08,85.95 13.11,85.95 15.24,83.82 17.78,83.82
WSTR12
  Top 0.406: 5.08,74.07 25.81,74.07 30.48,78.74 46.99,78.74 52.07,83.82 93.98,83.82 96.52,81.28 99.06,81.28
WSTR13
  Top 0.406: 5.08,78.03 13.41,78.03 13.97,77.47 21.59,77.47 22.86,76.2 25.4,76.2
WSTR14
  Top 0.406: 5.08,93.88 12.8,93.88 16.51,90.17 21.59,90.17 22.86,88.9 25.4,88.9
WSTR15
  Top 0.406: 5.08,89.92 14.22,89.92 15.24,88.9 17.78,88.9
WSTR16
  Top 0.406: 5.08,81.99 11.99,81.99 15.24,78.74 17.78,78.74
